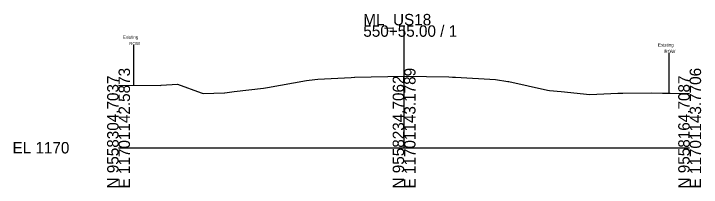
# Model space of a CAD drawing. Extents: x -75 to 1143, y -10 to 8583.
# Drawn here: x 974.3 to 1142.8, y 1340.3 to 1382.8 of the extents above; entities that cross this region are included whole.
import ezdxf

# ---------------------------------------------------------------- set-up
doc = ezdxf.new("R2010")
doc.units = 0
for name, color, linetype in [('Draft_XS_Grid', 7, 'Continuous'), ('Draft_XS_Text', 7, 'Continuous'), ('dsnCellElements', 7, 'Continuous'), ('dsnGeopakCellCrossSection', 7, 'Continuous'), ('dsnXsExistingGround', 7, 'Continuous')]:
    doc.layers.add(name, color=color, linetype=linetype)

msp = doc.modelspace()

# ---------------------------------------------------------------- linework, layer by layer
at = {"layer": 'dsnCellElements'}
for p, q in [((1003.68, 1375.15), (1003.68, 1365.31)), ((1134.89, 1373.21), (1134.89, 1363.37))]:
    msp.add_line(p, q, dxfattribs=at)
at = {"layer": 'dsnGeopakCellCrossSection'}
for p, q in [((1070, 1350), (1070, 1380)), ((1000, 1350), (1070, 1350)), ((1070, 1350), (1140, 1350))]:
    msp.add_line(p, q, dxfattribs=at)
at = {"layer": 'dsnXsExistingGround'}
msp.add_lwpolyline([(1000, 1365.32), (1010.24, 1365.28), (1010.43, 1365.3), (1014.41, 1365.59), (1020.22, 1363.46), (1020.72, 1363.28), (1025.93, 1363.48), (1026.09, 1363.48), (1028.37, 1363.75), (1035.57, 1364.59), (1036.55, 1364.77), (1046.07, 1366.46), (1048.09, 1366.72), (1048.89, 1366.82), (1057.01, 1367.23), (1057.83, 1367.27), (1057.93, 1367.27), (1070.02, 1367.56), (1080.96, 1367.35), (1081.83, 1367.33), (1082.56, 1367.29), (1092.43, 1366.71), (1095.45, 1366.27), (1095.69, 1366.24), (1105.18, 1364.14), (1105.66, 1364.04), (1108.51, 1363.74), (1115.5, 1363.01), (1122.4, 1363.36), (1122.93, 1363.38), (1123.58, 1363.39), (1130.74, 1363.43), (1133.31, 1363.39), (1135.21, 1363.36), (1140, 1363.31)], dxfattribs=at)

# ---------------------------------------------------------------- texts
at = {"layer": 'Draft_XS_Grid'}
msp.add_text('-', height=0.0001, dxfattribs=at).set_placement((1000, 1350))
at = {"layer": 'Draft_XS_Text'}
msp.add_text('Sta. 550+55.00 R1', height=0.02, dxfattribs=at).set_placement((1069.86, 1349.84))
at = {"layer": 'dsnCellElements'}
for s, p in [('Existing', (1001.05, 1376.73)), ('ROW', (1002.61, 1375.15)), ('Existing', (1132.27, 1374.79)), ('ROW', (1133.82, 1373.21))]:
    msp.add_text(s, height=0.787, dxfattribs=at).set_placement(p)
at = {"layer": 'dsnGeopakCellCrossSection'}
for s, p in [('ML_US18', (1060, 1380)), ('550+55.00 / 1', (1060, 1377.2)), ('EL 1170', (974, 1348.6))]:
    msp.add_text(s, height=2.8, dxfattribs=at).set_placement(p)
for s, p in [('E 11701142.5873', (1002.8, 1340)), ('E 11701143.1789', (1072.8, 1340)), ('E 11701143.7706', (1142.8, 1340)), ('N 9558304.7037', (1000, 1340)), ('N 9558234.7062', (1070, 1340)), ('N 9558164.7087', (1140, 1340))]:
    msp.add_text(s, height=2.8, rotation=90, dxfattribs=at).set_placement(p)

doc.saveas('drawing.dxf')
